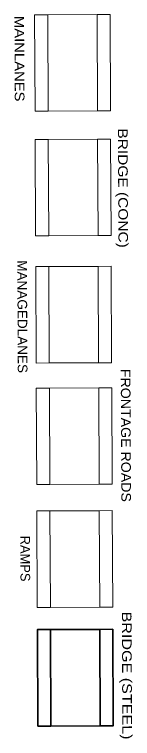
# Model space of a CAD drawing. Extents: x 2328590 to 2339576, y 6995086 to 7049864.
# Drawn here: x 2338594 to 2339576, y 7028555 to 7034568 of the extents above; entities that cross this region are included whole.
import ezdxf
from ezdxf.enums import TextEntityAlignment as Align

# ---------------------------------------------------------------- set-up
doc = ezdxf.new("R2010")
doc.units = 0
doc.header["$LTSCALE"] = 32
for name, color, linetype, lineweight in [('1', 7, 'Continuous', 13), ('14', 7, 'Continuous', 13), ('20', 7, 'Continuous', 13), ('21', 7, 'Continuous', 13), ('22', 7, 'Continuous', 13), ('23', 7, 'Continuous', 13), ('24', 7, 'Continuous', 13)]:
    doc.layers.add(name, color=color, linetype=linetype, lineweight=lineweight)

msp = doc.modelspace()

# ---------------------------------------------------------------- linework, layer by layer
at = {"layer": '1'}
for points in [[(2338870.34, 7034565.2), (2338873.94, 7033764.62), (2338765.44, 7033764.13), (2338761.83, 7034564.71)], [(2339280.89, 7034567.05), (2339284.5, 7033766.47), (2338873.94, 7033764.62), (2338870.34, 7034565.2)], [(2339389.4, 7034567.54), (2339393, 7033766.96), (2339284.5, 7033766.47), (2339280.89, 7034567.05)], [(2338875, 7033530.01), (2338878.61, 7032729.43), (2338770.1, 7032728.94), (2338766.5, 7033529.53)], [(2339285.56, 7033531.87), (2339289.16, 7032731.28), (2338878.61, 7032729.43), (2338875, 7033530.01)], [(2339394.06, 7033532.35), (2339397.67, 7032731.77), (2339289.16, 7032731.28), (2339285.56, 7033531.87)], [(2338879.75, 7032474.3), (2338883.36, 7031673.71), (2338774.86, 7031673.22), (2338771.25, 7032473.81)], [(2339290.31, 7032476.15), (2339293.92, 7031675.56), (2338883.36, 7031673.71), (2338879.75, 7032474.3)], [(2339398.82, 7032476.64), (2339402.42, 7031676.05), (2339293.92, 7031675.56), (2339290.31, 7032476.15)], [(2338884.3, 7031465.5), (2338887.91, 7030664.92), (2338779.4, 7030664.43), (2338775.79, 7031465.01)], [(2339294.86, 7031467.35), (2339298.46, 7030666.77), (2338887.91, 7030664.92), (2338884.3, 7031465.5)], [(2339403.36, 7031467.84), (2339406.97, 7030667.26), (2339298.46, 7030666.77), (2339294.86, 7031467.35)], [(2338888.9, 7030444.98), (2338892.5, 7029644.39), (2338784, 7029643.9), (2338780.39, 7030444.49)], [(2339299.45, 7030446.83), (2339303.06, 7029646.24), (2338892.5, 7029644.39), (2338888.9, 7030444.98)], [(2339407.96, 7030447.32), (2339411.56, 7029646.73), (2339303.06, 7029646.24), (2339299.45, 7030446.83)], [(2338893.33, 7029459.64), (2338896.94, 7028659.06), (2338788.44, 7028658.57), (2338784.83, 7029459.15)], [(2339303.89, 7029461.49), (2339307.5, 7028660.91), (2338896.94, 7028659.06), (2338893.33, 7029459.64)], [(2339412.4, 7029461.98), (2339416, 7028661.39), (2339307.5, 7028660.91), (2339303.89, 7029461.49)]]:
    msp.add_lwpolyline(points, close=True, dxfattribs=at)
at = {"layer": '14'}
for points in [[(2338870.34, 7034565.2), (2338761.83, 7034564.71), (2338765.44, 7033764.13), (2338873.94, 7033764.62)], [(2339280.89, 7034567.05), (2338870.34, 7034565.2), (2338873.94, 7033764.62), (2339284.5, 7033766.47)], [(2339389.4, 7034567.54), (2339280.89, 7034567.05), (2339284.5, 7033766.47), (2339393, 7033766.96)]]:
    msp.add_lwpolyline(points, close=True, dxfattribs=at)
at = {"layer": '20'}
for points in [[(2338875, 7033530.01), (2338766.5, 7033529.53), (2338770.1, 7032728.94), (2338878.61, 7032729.43)], [(2339285.56, 7033531.87), (2338875, 7033530.01), (2338878.61, 7032729.43), (2339289.16, 7032731.28)], [(2339394.06, 7033532.35), (2339285.56, 7033531.87), (2339289.16, 7032731.28), (2339397.67, 7032731.77)]]:
    msp.add_lwpolyline(points, close=True, dxfattribs=at)
at = {"layer": '21'}
for points in [[(2338879.75, 7032474.3), (2338771.25, 7032473.81), (2338774.86, 7031673.22), (2338883.36, 7031673.71)], [(2339290.31, 7032476.15), (2338879.75, 7032474.3), (2338883.36, 7031673.71), (2339293.92, 7031675.56)], [(2339398.82, 7032476.64), (2339290.31, 7032476.15), (2339293.92, 7031675.56), (2339402.42, 7031676.05)]]:
    msp.add_lwpolyline(points, close=True, dxfattribs=at)
at = {"layer": '22'}
for points in [[(2338884.3, 7031465.5), (2338775.79, 7031465.01), (2338779.4, 7030664.43), (2338887.91, 7030664.92)], [(2339294.86, 7031467.35), (2338884.3, 7031465.5), (2338887.91, 7030664.92), (2339298.46, 7030666.77)], [(2339403.36, 7031467.84), (2339294.86, 7031467.35), (2339298.46, 7030666.77), (2339406.97, 7030667.26)]]:
    msp.add_lwpolyline(points, close=True, dxfattribs=at)
at = {"layer": '23'}
for points in [[(2338888.9, 7030444.98), (2338780.39, 7030444.49), (2338784, 7029643.9), (2338892.5, 7029644.39)], [(2339299.45, 7030446.83), (2338888.9, 7030444.98), (2338892.5, 7029644.39), (2339303.06, 7029646.24)], [(2339407.96, 7030447.32), (2339299.45, 7030446.83), (2339303.06, 7029646.24), (2339411.56, 7029646.73)]]:
    msp.add_lwpolyline(points, close=True, dxfattribs=at)
at = {"layer": '24', "lineweight": 35}
for points in [[(2338893.33, 7029459.64), (2338784.83, 7029459.15), (2338788.44, 7028658.57), (2338896.94, 7028659.06)], [(2339303.89, 7029461.49), (2338893.33, 7029459.64), (2338896.94, 7028659.06), (2339307.5, 7028660.91)], [(2339412.4, 7029461.98), (2339303.89, 7029461.49), (2339307.5, 7028660.91), (2339416, 7028661.39)]]:
    msp.add_lwpolyline(points, close=True, dxfattribs=at)

# ---------------------------------------------------------------- texts
at = {"layer": '1'}
for s, width, p in [('MAINLANES', 1.15, (2338595.33, 7034200.13)), ('BRIDGE (CONC)', 1.2, (2339456.99, 7033125.62)), ('MANAGEDLANES', 1.05, (2338619.76, 7032058.23)), ('FRONTAGE ROADS', 1.1, (2339481.01, 7031072.34)), ('BRIDGE (STEEL)', 1.25, (2339489.98, 7029078.09))]:
    msp.add_text(s, height=80, rotation=270.258, dxfattribs=dict(at, width=width)).set_placement(p, align=Align.CENTER)
msp.add_text('RAMPS', height=80, rotation=270.258, dxfattribs=at).set_placement((2338643.58, 7030049.27), align=Align.CENTER)

doc.saveas('drawing.dxf')
